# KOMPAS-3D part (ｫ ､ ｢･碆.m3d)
File: created 04.01.2016 18:05:13, last saved 27.07.2016 13:38:12.
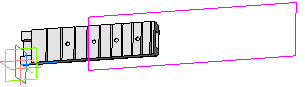
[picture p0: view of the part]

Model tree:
1. Эскиз:1
2. Операция выдавливания:1
     Расстояние 1 = 20
3. Эскиз:2
4. Операция выдавливания:2
     Расстояние 1 = 400
5. Эскиз:3
6. Вырезать элемент выдавливания:1
     Расстояние 1 = 70
7. Эскиз:4
8. Вырезать элемент выдавливания:2
     Расстояние 1 = 2
9. Эскиз:5
10. Эскиз:6
11. Вырезать элемент выдавливания:3
     Расстояние 2 = 40; Расстояние 1 = 36
12. Эскиз:7
13. Вырезать элемент выдавливания:4
     Расстояние 1 = 50
14. Эскиз:8
15. Эскиз:9
16. Вырезать элемент выдавливания:5
     Расстояние 1 = 30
